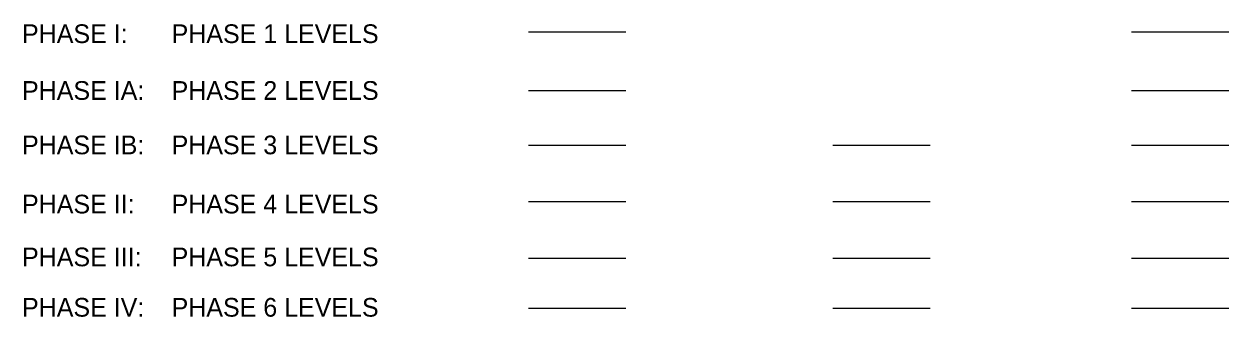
# Model space of a CAD drawing. Extents: x 2133551 to 2156187, y 140366 to 148242.
# Drawn here: x 2133551 to 2139995, y 145856 to 147423 of the extents above; entities that cross this region are included whole.
import ezdxf

# ---------------------------------------------------------------- set-up
doc = ezdxf.new("R2010")
doc.units = 0
for name, color, linetype in [('PR_Phasing_Bridge_3', 7, 'Continuous'), ('PR_Phasing_Bridge_4', 7, 'Continuous'), ('PR_Phasing_Bridge_5', 7, 'Continuous'), ('PR_Phasing_Bridge_6', 7, 'Continuous'), ('PR_Phasing_Pavement_1', 7, 'Continuous'), ('PR_Phasing_Pavement_2', 7, 'Continuous'), ('PR_Phasing_Pavement_3', 7, 'Continuous'), ('PR_Phasing_Pavement_4', 7, 'Continuous'), ('PR_Phasing_Pavement_5', 7, 'Continuous'), ('PR_Phasing_Pavement_6', 7, 'Continuous'), ('PR_Shading_Bridge_Phase_1', 7, 'Continuous'), ('PR_Shading_Bridge_Phase_2', 7, 'Continuous'), ('PR_Shading_Bridge_Phase_3', 7, 'Continuous'), ('PR_Shading_Bridge_Phase_4', 7, 'Continuous'), ('PR_Shading_Bridge_Phase_5', 7, 'Continuous'), ('PR_Shading_Bridge_Phase_6', 7, 'Continuous'), ('PR_Shading_Pavement_Phase_1', 7, 'Continuous'), ('PR_Shading_Pavement_Phase_2', 7, 'Continuous'), ('PR_Shading_Pavement_Phase_3', 7, 'Continuous'), ('PR_Shading_Pavement_Phase_4', 7, 'Continuous'), ('PR_Shading_Pavement_Phase_5', 7, 'Continuous'), ('PR_Shading_Pavement_Phase_6', 7, 'Continuous')]:
    doc.layers.add(name, color=color, linetype=linetype)

msp = doc.modelspace()

# ---------------------------------------------------------------- linework, layer by layer
at = {"layer": 'PR_Phasing_Bridge_3'}
msp.add_line((2138397.4, 146773.2), (2137876.7, 146773.2), dxfattribs=at)
at = {"layer": 'PR_Phasing_Bridge_4'}
msp.add_line((2138397.4, 146471.3), (2137876.7, 146471.3), dxfattribs=at)
at = {"layer": 'PR_Phasing_Bridge_5'}
msp.add_line((2138397.4, 146169.5), (2137876.7, 146169.5), dxfattribs=at)
at = {"layer": 'PR_Phasing_Bridge_6'}
msp.add_line((2138397.4, 145900.7), (2137876.7, 145900.7), dxfattribs=at)
at = {"layer": 'PR_Shading_Bridge_Phase_1'}
msp.add_line((2139995.4, 147381), (2139474.7, 147381), dxfattribs=at)
at = {"layer": 'PR_Shading_Bridge_Phase_2'}
msp.add_line((2139995.4, 147066.7), (2139474.7, 147066.7), dxfattribs=at)
at = {"layer": 'PR_Shading_Bridge_Phase_3'}
msp.add_line((2139995.4, 146773.2), (2139474.7, 146773.2), dxfattribs=at)
at = {"layer": 'PR_Shading_Bridge_Phase_4'}
msp.add_line((2139995.4, 146471.3), (2139474.7, 146471.3), dxfattribs=at)
at = {"layer": 'PR_Shading_Bridge_Phase_5'}
msp.add_line((2139995.4, 146169.5), (2139474.7, 146169.5), dxfattribs=at)
at = {"layer": 'PR_Shading_Bridge_Phase_6'}
msp.add_line((2139995.4, 145900.7), (2139474.7, 145900.7), dxfattribs=at)
at = {"layer": 'PR_Shading_Pavement_Phase_1'}
msp.add_line((2136770.4, 147381), (2136249.8, 147381), dxfattribs=at)
at = {"layer": 'PR_Shading_Pavement_Phase_2'}
msp.add_line((2136770.4, 147066.7), (2136249.8, 147066.7), dxfattribs=at)
at = {"layer": 'PR_Shading_Pavement_Phase_3'}
msp.add_line((2136770.4, 146773.2), (2136249.8, 146773.2), dxfattribs=at)
at = {"layer": 'PR_Shading_Pavement_Phase_4'}
msp.add_line((2136770.4, 146471.3), (2136249.8, 146471.3), dxfattribs=at)
at = {"layer": 'PR_Shading_Pavement_Phase_5'}
msp.add_line((2136770.4, 146169.5), (2136249.8, 146169.5), dxfattribs=at)
at = {"layer": 'PR_Shading_Pavement_Phase_6'}
msp.add_line((2136770.4, 145900.7), (2136249.8, 145900.7), dxfattribs=at)

# ---------------------------------------------------------------- texts
at = {"layer": 'PR_Phasing_Pavement_1'}
for s, p in [('PHASE I:', (2133540, 147321.9)), ('PHASE 1 LEVELS', (2134340, 147321.9))]:
    msp.add_text(s, height=100, dxfattribs=at).set_placement(p)
at = {"layer": 'PR_Phasing_Pavement_2'}
for s, p in [('PHASE IA:', (2133540, 147018)), ('PHASE 2 LEVELS', (2134340, 147018))]:
    msp.add_text(s, height=100, dxfattribs=at).set_placement(p)
at = {"layer": 'PR_Phasing_Pavement_3'}
for s, p in [('PHASE IB:', (2133540, 146726.7)), ('PHASE 3 LEVELS', (2134340, 146726.7))]:
    msp.add_text(s, height=100, dxfattribs=at).set_placement(p)
at = {"layer": 'PR_Phasing_Pavement_4'}
for s, p in [('PHASE II:', (2133540, 146410.1)), ('PHASE 4 LEVELS', (2134340, 146410.1))]:
    msp.add_text(s, height=100, dxfattribs=at).set_placement(p)
at = {"layer": 'PR_Phasing_Pavement_5'}
for s, p in [('PHASE III:', (2133540, 146127.3)), ('PHASE 5 LEVELS', (2134340, 146127.3))]:
    msp.add_text(s, height=100, dxfattribs=at).set_placement(p)
at = {"layer": 'PR_Phasing_Pavement_6'}
for s, p in [('PHASE IV:', (2133540, 145857.7)), ('PHASE 6 LEVELS', (2134340, 145857.7))]:
    msp.add_text(s, height=100, dxfattribs=at).set_placement(p)

doc.saveas('drawing.dxf')
